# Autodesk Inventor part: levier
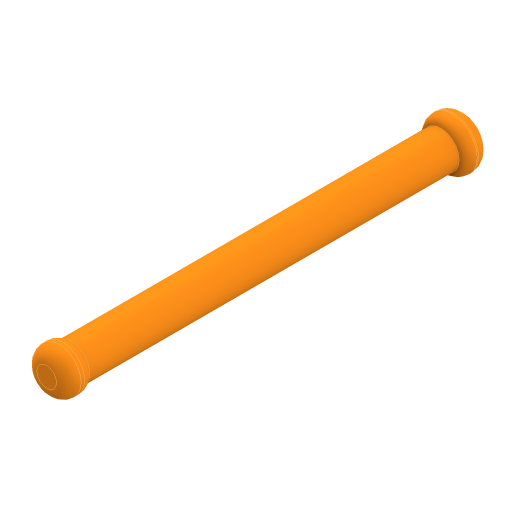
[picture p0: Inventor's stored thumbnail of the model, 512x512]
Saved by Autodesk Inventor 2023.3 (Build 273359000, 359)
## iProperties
Created: 2024-11
Part Number: levier
Material: Générique
Description: STEP AP203
Document SubType Name: Modeling
Designer: Thier
Density: 1 g/cm^3
Appearance: Orange
Sending System: SolidWorks 2017
Preprocessor: SwSTEP 2.0
Title: levier.STEP
Revision Number: ANY
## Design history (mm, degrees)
feature "Congé5"
node "Solide1"
